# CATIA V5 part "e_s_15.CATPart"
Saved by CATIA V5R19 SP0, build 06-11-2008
Part number: e/s_15
Bounding box of the stored display mesh (mm): x -78 to 78, y 0 to 10, z -78 to 78
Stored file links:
  C:\Users\Thinkmotion2\Desktop\Pack 2\CFAO_2010\abaussand\CFAO_abaussand_Catia_V5R20\e_s_15.CATPart
  C:\Users\Thinkmotion2\Desktop\Pack 2\CFAO_2010\abaussand\CFAO_abaussand_Catia_V5R20\corps_12.CATPart
  C:\Users\Alex\IFMA\2A\CFAO\pompe\pompe.CATProduct
  C:\Users\Thinkmotion2\Desktop\Pack 2\CFAO_2010\abaussand\CFAO_abaussand_Catia_V5R20\abaussand_2.CATProduct
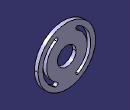
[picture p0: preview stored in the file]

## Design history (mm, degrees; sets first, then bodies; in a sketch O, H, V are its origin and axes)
External parameters (linked from other documents)
  External.Positionnement_piston = 60 mm
Body1 (main body)
  Sketch1 on zx-plane, origin (0, 0, 0), H (-1, 0, 0), V (0, 0, 1)
    circle A1 centre (0, 0) radius 78
    circle A2 centre (0, 0) radius 25
    radius A1 = 78
    radius A2 = 25
  Pad1: profile Sketch1, direction (0, 1, 0), length 10
  Sketch2 on end face of Pad1, origin (0, 10, 0), H (-1, 0, 0), V (0, 0, 1)
    arc A1 centre (0, 0) radius 65 from (-31.5584, 56.8249) to (-31.5584, -56.8249) ccw
    arc A2 centre (0, 0) radius 55 from (-26.7032, 48.0826) to (-26.7032, -48.0826) ccw
    arc A3 centre (-29.1308, 52.4538) radius 5 from (-31.5584, 56.8249) to (-26.7032, 48.0826) cw
    point P2 (-31.5584, 56.8249)
    point P3 (-26.7032, 48.0826)
    arc A4 centre (-29.1308, -52.4538) radius 5 from (-26.7032, -48.0826) to (-31.5584, -56.8249) cw
    radius A2 = 55 {= External.Positionnement_piston - 5mm}
    radius A1 = 65 {= External.Positionnement_piston + 5mm}
    distance P3 P2 = 10
    radius A4 = 5
    tangency: A3 A1
  Pocket1: profile Sketch2, direction (0, -1, 0), up to start face of Pad1
  Mirror1: of Pocket1, about yz-plane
